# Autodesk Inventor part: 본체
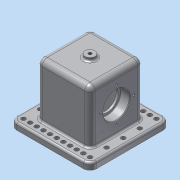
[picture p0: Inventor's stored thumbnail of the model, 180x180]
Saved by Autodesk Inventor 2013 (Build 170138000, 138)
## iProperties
Created: 2018-11
Part Number: 본체
Material: 알루미늄 6061
Document SubType Name: Modeling
Designer: dgall
Density: 2.71 g/cm^3
Mass: 1020.76 g
Surface Area: 777.082 cm^2
Volume: 376.663 cm^3
Author: dgall
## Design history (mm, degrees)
sketch "스케치1"
  geometry: L1 (-40, 40)-(40, 40); L2 (40, 40)-(40, -40); L3 (40, -40)-(-40, -40); L4 (-40, -40)-(-40, 40); 3 further points
  constraints: 8 end point, 2 midpoint, 2 parallel, 1 horizontal, 1 horizontal alignment, 1 perpendicular, 1 vertical alignment
  dimensions: "d0" = 80 distance of L2.end L3.end; "d1" = 80 distance of L1.end L2.end
extrude "돌출1" new body sketch "스케치1" stored distance "d2" = 90; taper "d3" = 0 deg
sketch "스케치3"
  geometry: L1 (23, 35)-(-23, 35); L2 (-23, 35)-(-23, -45); L3 (-23, -45)-(23, -45); L4 (23, -45)-(23, 35); L5 (40, -45)-(-40, -45) reference; 3 further points
  constraints: 8 end point, 3 midpoint, 2 parallel, 1 horizontal, 1 perpendicular, 1 vertical alignment
  dimensions: "d6" = 46 distance of L2.end L3.end; "d8" = 80 distance of L1.end L2.end
sketch "스케치4"
  geometry: L1 (90, 80)-(90, 0) reference; C1 r 20 at (42, 40); 1 further point
  constraints: 1 centre point, 1 horizontal alignment
  dimensions: "d11" = 40 diameter of C1; "d12" = 48 distance from line of L1 C1.centre
extrude "돌출3" cut sketch "스케치4" distance "d13" = 14; taper "d14" = 0 deg
hole "구멍1" diameter "d17" = 33; stored, may be unused: countersink angle "d21" = 90 deg, drill point angle "d23" = 118 deg; dims "d15" = 10, "d16" = 10, "d18" = 6, "d19" = 4, "d20" = 2, "d22" = 8
sketch "스케치5" dims "d24" = 52
  geometry: C1 r 20 at (42, 40) reference; C2 r 2 at (16, 40); 2 further points
  constraints: 2 horizontal alignment, 1 centre point, 1 coincident, 2 other
  dimensions: "d25" = 4 diameter of C2
hole "구멍2" sketch "스케치5" at (16, 40) diameter "d26" = 3.242; stored, may be unused: countersink angle "d30" = 90 deg, drill point angle "d32" = 118 deg; dims "d27" = 8, "d28" = 4, "d29" = 2, "d31" = 10
node "작업 평면1"
sketch "스케치6"
  geometry: L1 (-60, 60)-(60, 60); L2 (60, 60)-(60, -60); L3 (60, -60)-(-60, -60); L4 (-60, -60)-(-60, 60); C1 r 3.3 at (-50, -50); C2 r 3.3 at (50, -50); 3 further points
  constraints: 8 end point, 2 centre point, 2 midpoint, 2 parallel, 1 horizontal, 1 horizontal alignment, 1 perpendicular, 1 vertical alignment
  dimensions: "d37" = 120 distance of L2.end L3.end; "d38" = 120 distance of L1.end L2.end; "d39" = 6.6 diameter of C1; "d40" = 10 distance from line of L3 C1.centre; "d41" = 10 distance from line of L4 C1.centre; "d49" = 6.6 diameter of C2; "d50" = 10 distance from line of L3 C2.centre; "d51" = 10 distance from line of L2 C2.centre
extrude "돌출4" join sketch "스케치6" distance "d42" = 10; taper "d43" = 0 deg
extrude "돌출5" cut sketch "스케치6" stored distance "d44" = 10; taper "d45" = 0 deg
extrude "돌출6" cut sketch "스케치6" stored distance "d52" = 10; taper "d53" = 0 deg
extrude "돌출7" cut sketch "스케치3" stored distance "d63" = 60; taper "d64" = 0 deg
sketch "스케치7"
  geometry: C1 r 7.5 at (0, 0); 1 further point
  constraints: 1 centre point, 1 coincident
  dimensions: "d65" = 15 diameter of C1
extrude "돌출8" join sketch "스케치7" distance "d66" = 5; taper "d67" = 0 deg
fillet "모깎기1" dims "d68" = 8
fillet "모깎기2" dims "d69" = 8
hole "구멍3" diameter "d72" = 4.917; stored, may be unused: countersink angle "d76" = 90 deg, drill point angle "d78" = 118 deg; dims "d70" = 10, "d71" = 10, "d73" = 8, "d74" = 4, "d75" = 2, "d77" = 10
fillet "모깎기4" dims "d80" = 3
fillet "모깎기5" dims "d81" = 3
fillet "모깎기6" dims "d82" = 3
fillet "모깎기7" dims "d83" = 3
fillet "모깎기8" dims "d84" = 0.6
chamfer "모따기1" distance "d85" = 1; stored, may be unused: second distance "d86" = 2, angle "d87" = 45 deg
sketch "스케치8"
  geometry: L1 (-28, 82)-(92, 82) reference; 2 further points
  constraints: 1 vertical alignment, 1 other
  dimensions: "d88" = 48 distance from line of L1 point (32, 34)
feature "엠보싱1" sketch "스케치8" dims "d14" = 0, "d89" = 0.5, "d90" = 0
fillet "모깎기9" dims "d91" = 10
fillet "모깎기10" dims "d92" = 3
node "솔리드1"
pattern_circular "원형 패턴1" dims angle "d34" = 360 deg
mirror "대칭1"
pattern_linear "직사각형 패턴2" dims "d56" = 10
pattern_linear "직사각형 패턴3" dims "d59" = 25
pattern_linear "직사각형 패턴4" dims "d62" = 25
mirror "대칭2"
other parameters: "d36" = -45
